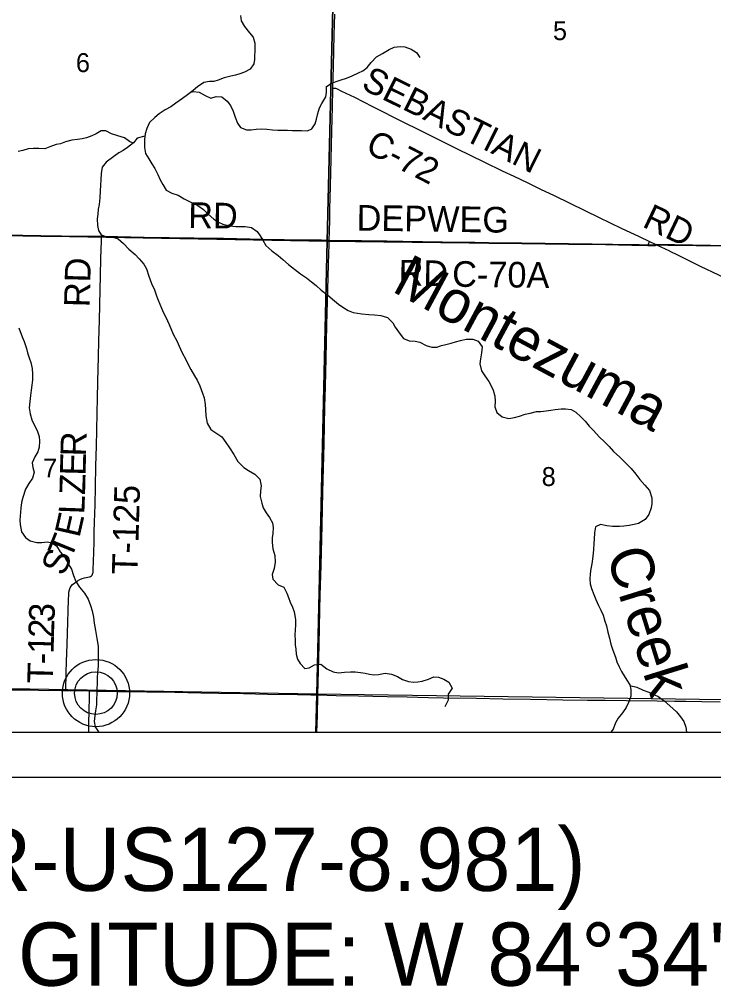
# Model space of a CAD drawing. Extents: x -38.1 to 35.9, y -2.7 to 28.5.
# Drawn here: x 22.334 to 23.873, y 12.367 to 14.509 of the extents above; entities that cross this region are included whole.
import ezdxf

# ---------------------------------------------------------------- set-up
doc = ezdxf.new("R2010")
doc.units = 0
for name, color, linetype in [('GM_X_City_Street_Text', 7, 'Continuous'), ('GM_X_County_ROW', 7, 'Continuous'), ('GM_X_Interchange_Ramps', 7, 'Continuous'), ('GM_X_Major_River_Text', 7, 'Continuous'), ('GM_X_Minor_Lake', 7, 'Continuous'), ('GM_X_Minor_River', 7, 'Continuous'), ('GM_X_Section', 7, 'Continuous'), ('GM_X_State_Location', 7, 'Continuous'), ('GM_X_Township', 7, 'Continuous'), ('GM_X_US_Location', 7, 'Continuous'), ('GM_X_US_Route', 7, 'Continuous'), ('SH_Border', 7, 'Continuous'), ('SH_Data', 7, 'Continuous')]:
    doc.layers.add(name, color=color, linetype=linetype)

msp = doc.modelspace()

# ---------------------------------------------------------------- linework, layer by layer
at = {"layer": 'GM_X_City_Street_Text'}
for points in [[(23.0287, 14.3566), (23.03, 14.4044), (23.0321, 14.4746), (23.0332, 14.5205)], [(23.0207, 14.0188), (23.022, 14.0627), (23.0222, 14.0788), (23.0224, 14.0906), (23.023, 14.1122), (23.0242, 14.1689), (23.0264, 14.2615), (23.0279, 14.3149), (23.0286, 14.3534), (23.0287, 14.3566)], [(23.0287, 14.3566), (23.0304, 14.3567), (23.0319, 14.3567), (23.0328, 14.3567), (23.0338, 14.3565), (23.0348, 14.3563), (23.0368, 14.3554), (23.0481, 14.3501), (23.0765, 14.3361), (23.1165, 14.316), (23.1376, 14.3054), (23.1648, 14.2918), (23.188, 14.2798), (23.217, 14.2656), (23.2714, 14.2382), (23.3025, 14.2226), (23.3651, 14.1922), (23.4037, 14.1737), (23.4295, 14.1613), (23.4592, 14.1472), (23.4889, 14.133), (23.5192, 14.1185), (23.5869, 14.0857), (23.6188, 14.0703), (23.6674, 14.0467), (23.7073, 14.0278), (23.7303, 14.0169)], [(21.9177, 14.0374), (21.9429, 14.0367), (21.9873, 14.0362), (22.0447, 14.0351), (22.0942, 14.0343), (22.1484, 14.0334), (22.1956, 14.0323), (22.2832, 14.031), (22.3422, 14.0297), (22.3821, 14.029), (22.4276, 14.0284), (22.5162, 14.0274)], [(22.5162, 14.0274), (22.5224, 14.0273), (22.6112, 14.0255), (22.7218, 14.0237), (22.7522, 14.0232), (22.787, 14.0228), (22.8454, 14.0218), (22.8745, 14.021), (22.9684, 14.0196), (23.0035, 14.0189), (23.0162, 14.0188), (23.0207, 14.0188), (23.0927, 14.0177), (23.1488, 14.0168), (23.184, 14.0165), (23.2716, 14.0153), (23.2727, 14.0153)], [(22.9956, 13.013), (22.9968, 13.0663), (22.9975, 13.093), (22.9991, 13.1601), (22.9999, 13.2029), (23.0009, 13.2334), (23.0027, 13.3005), (23.0051, 13.3881), (23.0065, 13.462), (23.0089, 13.5421), (23.0094, 13.5688), (23.0112, 13.6509), (23.0124, 13.6962), (23.0138, 13.7577), (23.0157, 13.8323), (23.0179, 13.9099), (23.0193, 13.9664), (23.0204, 14.0111), (23.0207, 14.0188)], [(23.2727, 14.0153), (23.3437, 14.014), (23.3741, 14.0135), (23.4474, 14.0125), (23.551, 14.0113), (23.6034, 14.0107), (23.6914, 14.009)], [(23.6914, 14.009), (23.6935, 14.009), (23.7264, 14.0084), (23.7326, 14.0083), (23.7379, 14.0082), (23.7407, 14.0081), (23.7425, 14.0082), (23.7439, 14.0083), (23.7451, 14.0088), (23.746, 14.0095)], [(23.7264, 14.0084), (23.7275, 14.0097), (23.7284, 14.0112), (23.7291, 14.0129), (23.7297, 14.0147), (23.7303, 14.0169)], [(23.7303, 14.0169), (23.7418, 14.0115), (23.746, 14.0095)], [(23.746, 14.0095), (23.7556, 14.005), (23.7744, 13.9959), (23.7752, 13.9955)], [(23.7752, 13.9955), (23.7925, 13.9872), (23.8427, 13.9625), (23.8836, 13.9429), (23.9373, 13.9169), (24.0117, 13.8809), (24.0233, 13.8753)], [(22.9935, 12.9308), (22.9945, 12.9673), (22.9956, 13.013)]]:
    msp.add_lwpolyline(points, dxfattribs=at)
at = {"layer": 'GM_X_County_ROW'}
msp.add_line((22.5039, 13.0171), (22.5039, 13.0171), dxfattribs=at)
at = {"layer": 'GM_X_Interchange_Ramps'}
for p, q in [((22.437, 13.0226), (22.4897, 13.0219)), ((22.4897, 13.0219), (22.4979, 13.0218))]:
    msp.add_line(p, q, dxfattribs=at)
for points in [[(21.893, 13.0338), (21.8997, 13.0337), (21.9581, 13.0327), (21.9941, 13.0317), (22.0314, 13.0308), (22.0637, 13.0299), (22.1177, 13.0288), (22.1917, 13.0273), (22.2252, 13.0264), (22.2867, 13.0251), (22.3091, 13.0247), (22.3122, 13.0246), (22.3352, 13.0244), (22.3581, 13.024), (22.3768, 13.0237), (22.4268, 13.0227), (22.437, 13.0226)], [(22.4979, 13.0218), (22.5072, 13.0216), (22.5287, 13.0213), (22.554, 13.0209), (22.578, 13.0205), (22.6168, 13.0201), (22.6498, 13.0196), (22.7361, 13.0178), (22.7752, 13.0171), (22.8311, 13.0159), (22.8839, 13.0148), (22.9503, 13.0139), (22.9801, 13.0133), (22.9956, 13.013), (23.0365, 13.0121), (23.0858, 13.0111), (23.1488, 13.0096), (23.1935, 13.0087), (23.2407, 13.0077), (23.2743, 13.0068), (23.3469, 13.0056), (23.4058, 13.0048), (23.4667, 13.0036), (23.5385, 13.0024), (23.593, 13.0018), (23.6321, 13.0014), (23.6793, 13.0008), (23.7477, 12.9997), (23.7855, 12.9992), (23.811, 12.9989), (23.8464, 12.9983), (23.8868, 12.998)]]:
    msp.add_lwpolyline(points, dxfattribs=at)
at = {"layer": 'GM_X_Major_River_Text'}
msp.add_line((22.4897, 13.0219), (22.437, 13.0226), dxfattribs=at)
for points in [[(22.437, 13.0226), (22.4379, 13.0626), (22.4387, 13.0865), (22.4402, 13.1255), (22.4411, 13.1498), (22.4431, 13.2235), (22.4435, 13.2353), (22.444, 13.2409), (22.4452, 13.2459), (22.447, 13.25), (22.4493, 13.2538), (22.4523, 13.2572), (22.457, 13.2614), (22.4627, 13.2654), (22.4682, 13.2685), (22.4734, 13.2708), (22.4783, 13.2722), (22.4863, 13.2736), (22.4898, 13.2745), (22.492, 13.2752), (22.4939, 13.2765), (22.4953, 13.2782), (22.4966, 13.2807), (22.4971, 13.2824), (22.4974, 13.2842), (22.498, 13.2903), (22.4988, 13.3091), (22.4993, 13.3287), (22.4998, 13.352), (22.5002, 13.3743), (22.5008, 13.3956), (22.5019, 13.4338), (22.5028, 13.4741), (22.5038, 13.5195), (22.505, 13.5642), (22.5056, 13.5984), (22.5066, 13.6381), (22.507, 13.6692), (22.5082, 13.7071), (22.5097, 13.7617), (22.5105, 13.7972), (22.5116, 13.8425), (22.5131, 13.9102), (22.5138, 13.9419), (22.5148, 13.9792), (22.5159, 14.0183), (22.516, 14.0214), (22.5162, 14.0274)], [(22.4879, 12.9308), (22.4883, 12.9566), (22.4886, 12.9721), (22.4895, 13.0151), (22.4897, 13.0219)]]:
    msp.add_lwpolyline(points, dxfattribs=at)
at = {"layer": 'GM_X_Section'}
for points in [[(22.8245, 14.5174), (22.8258, 14.5056), (22.8331, 14.4929), (22.8442, 14.4786), (22.8519, 14.469), (22.8558, 14.4563), (22.856, 14.4465), (22.8554, 14.4199), (22.8537, 14.41), (22.8458, 14.3984), (22.8327, 14.3915), (22.8228, 14.3883), (22.8132, 14.3855), (22.8029, 14.3827), (22.788, 14.3796), (22.775, 14.3742), (22.7651, 14.3714), (22.7552, 14.3708), (22.7433, 14.3688), (22.7287, 14.3593), (22.719, 14.3511), (22.7067, 14.3419), (22.6954, 14.3334), (22.6812, 14.3235), (22.6696, 14.315), (22.6573, 14.3081), (22.6442, 14.2992), (22.6345, 14.2915), (22.6225, 14.2803), (22.6165, 14.2672), (22.6128, 14.2551), (22.6114, 14.243), (22.6114, 14.2247), (22.6137, 14.2118), (22.6211, 14.1998), (22.6277, 14.1886), (22.6343, 14.1782), (22.6408, 14.1652), (22.6459, 14.1533), (22.6521, 14.1433), (22.6594, 14.1302), (22.6722, 14.1238), (22.6858, 14.1193), (22.6997, 14.1114), (22.7098, 14.1059), (22.72, 14.1011), (22.7297, 14.0967), (22.7421, 14.088), (22.7525, 14.0775), (22.7652, 14.0666), (22.7753, 14.0595), (22.7851, 14.0555), (22.8006, 14.0518), (22.8142, 14.0503), (22.8347, 14.0498), (22.8483, 14.0476), (22.8614, 14.0394), (22.8681, 14.0297), (22.8736, 14.0197), (22.8801, 14.0078)], [(22.7145, 14.3477), (22.7201, 14.3488), (22.7326, 14.3474), (22.7457, 14.3403), (22.7582, 14.3343), (22.77, 14.3382), (22.7829, 14.3375), (22.7949, 14.3278), (22.8019, 14.3177), (22.808, 14.3054), (22.8123, 14.2924), (22.8177, 14.279), (22.824, 14.2694), (22.8375, 14.2641), (22.8478, 14.2643), (22.8588, 14.2655), (22.8714, 14.266), (22.8824, 14.2654), (22.8949, 14.2643), (22.907, 14.2637), (22.9169, 14.2635), (22.9283, 14.2636), (22.9393, 14.263), (22.9591, 14.2625), (22.9727, 14.2618), (22.9823, 14.2666), (22.9898, 14.2774), (22.9927, 14.288), (22.9956, 14.3005), (22.9993, 14.3125), (23.0041, 14.3227), (23.0135, 14.3373), (23.0149, 14.3475), (23.0151, 14.3597), (23.0252, 14.3667), (23.0359, 14.3714), (23.047, 14.3749), (23.0592, 14.3784), (23.0715, 14.3839), (23.0853, 14.39), (23.0953, 14.3944), (23.105, 14.4021), (23.114, 14.4133), (23.1256, 14.426), (23.1387, 14.4329), (23.1533, 14.4421), (23.1649, 14.4475), (23.1782, 14.4483), (23.1884, 14.4481), (23.2027, 14.4425), (23.2143, 14.435), (23.2217, 14.4242)], [(22.5863, 14.2344), (22.5786, 14.238), (22.567, 14.2462), (22.5523, 14.2511), (22.5387, 14.2556), (22.5256, 14.2616), (22.5157, 14.2622), (22.5045, 14.2556), (22.4949, 14.2505), (22.4831, 14.2462), (22.4731, 14.2442), (22.4628, 14.2425), (22.4503, 14.2409), (22.4365, 14.2378), (22.4254, 14.2335), (22.4155, 14.2314), (22.4021, 14.2268), (22.391, 14.2221), (22.3777, 14.2228), (22.3659, 14.223), (22.3534, 14.2218), (22.3419, 14.2186), (22.3316, 14.2158)], [(22.6122, 14.2502), (22.5955, 14.246), (22.5873, 14.2352), (22.5741, 14.2248), (22.5641, 14.2186), (22.5545, 14.2131), (22.5433, 14.205), (22.5267, 14.1924), (22.5177, 14.1816), (22.5155, 14.1672), (22.5145, 14.1536), (22.5138, 14.1418), (22.5132, 14.1293), (22.5128, 14.1133), (22.511, 14.0985), (22.5092, 14.0883), (22.5082, 14.0773), (22.5069, 14.0671), (22.5073, 14.0523), (22.5093, 14.0416), (22.5156, 14.0319), (22.5261, 14.0279), (22.539, 14.0272), (22.553, 14.0231), (22.5653, 14.0126), (22.5768, 13.9998), (22.591, 13.988), (22.5999, 13.9783), (22.6099, 13.9667), (22.6161, 13.9563), (22.6211, 13.9402), (22.6272, 13.9241), (22.6333, 13.9099), (22.638, 13.8969), (22.6419, 13.8869), (22.6495, 13.8693), (22.6539, 13.8589), (22.6586, 13.8493), (22.6662, 13.8328), (22.6753, 13.8117), (22.6829, 13.7967), (22.6909, 13.7786), (22.6956, 13.769), (22.7022, 13.7575), (22.7065, 13.7479), (22.7142, 13.7336), (22.7226, 13.7194), (22.7281, 13.7098), (22.7343, 13.6971), (22.74, 13.681), (22.7436, 13.671), (22.7456, 13.6561), (22.7464, 13.6447), (22.7473, 13.6306), (22.7507, 13.6146), (22.7588, 13.6007), (22.7696, 13.5932), (22.7827, 13.5842), (22.7916, 13.5718), (22.8001, 13.5602), (22.8096, 13.5452), (22.818, 13.5302), (22.8318, 13.5166), (22.8419, 13.5102), (22.8562, 13.5019), (22.8673, 13.4907), (22.8697, 13.4758), (22.8687, 13.4651), (22.868, 13.4522), (22.8711, 13.4373), (22.8747, 13.4274), (22.8809, 13.4162), (22.8887, 13.4061), (22.8952, 13.3938), (22.8969, 13.3839), (22.8959, 13.3706), (22.8945, 13.3608), (22.8943, 13.3509), (22.8955, 13.3368), (22.9001, 13.3218), (22.9013, 13.307), (22.8991, 13.293), (22.8943, 13.2798), (22.8959, 13.2694), (22.9075, 13.257), (22.9202, 13.2514), (22.9272, 13.2383), (22.9304, 13.2287), (22.9343, 13.2184), (22.9394, 13.2072), (22.9434, 13.1969), (22.9464, 13.1797), (22.9462, 13.1675), (22.9456, 13.1569), (22.9449, 13.1455), (22.9451, 13.1349), (22.9456, 13.1242), (22.9469, 13.1143), (22.9474, 13.1036), (22.9506, 13.0925), (22.9561, 13.0825)], [(22.8801, 14.0078), (22.8935, 13.9961), (22.9078, 13.9862), (22.9182, 13.9769), (22.9305, 13.966), (22.944, 13.9558), (22.957, 13.9456), (22.9705, 13.9362), (22.9813, 13.9276), (22.9918, 13.9197), (23.0029, 13.9089), (23.0168, 13.8987), (23.028, 13.8889), (23.041, 13.8783), (23.053, 13.8697), (23.0628, 13.8645), (23.0737, 13.8597), (23.0835, 13.858), (23.0934, 13.8566), (23.1085, 13.8555), (23.1214, 13.8549), (23.1354, 13.8534), (23.1498, 13.8485), (23.1617, 13.8365), (23.1668, 13.8269), (23.1782, 13.8118), (23.1856, 13.8021), (23.198, 13.7973), (23.2113, 13.7962), (23.2215, 13.7937), (23.2358, 13.7869), (23.2479, 13.7832), (23.2589, 13.7833), (23.2696, 13.7865), (23.2792, 13.789), (23.291, 13.7921), (23.3009, 13.7946), (23.3116, 13.7974), (23.3242, 13.8005), (23.3387, 13.8006), (23.3511, 13.7961), (23.3596, 13.7834), (23.3585, 13.7701), (23.3556, 13.7572), (23.3546, 13.7462), (23.3584, 13.7309), (23.3658, 13.7193), (23.3742, 13.707), (23.3797, 13.6974), (23.3841, 13.6878), (23.3876, 13.6747), (23.3881, 13.6637), (23.3878, 13.6512), (23.3925, 13.6385), (23.404, 13.6284), (23.4184, 13.6254), (23.4314, 13.6274), (23.4425, 13.6302), (23.4551, 13.6344), (23.4662, 13.6372), (23.4799, 13.6403), (23.4898, 13.6409), (23.5012, 13.6418), (23.5115, 13.6434), (23.5214, 13.6451), (23.5347, 13.6463), (23.5446, 13.6465), (23.5571, 13.6447), (23.5672, 13.6391), (23.5784, 13.629), (23.5881, 13.6189), (23.597, 13.6084), (23.6062, 13.5983), (23.6192, 13.5847), (23.6304, 13.5734), (23.6412, 13.5629), (23.6508, 13.5521), (23.665, 13.5396), (23.6795, 13.5244), (23.6895, 13.5143), (23.6999, 13.5015), (23.7087, 13.4899), (23.7199, 13.4771), (23.7302, 13.4655), (23.7356, 13.4494), (23.7357, 13.4372), (23.734, 13.427), (23.7287, 13.4126), (23.7205, 13.4018), (23.7062, 13.3926), (23.6963, 13.3905), (23.6856, 13.3885), (23.6735, 13.3869), (23.6639, 13.3856), (23.6487, 13.3859), (23.6355, 13.3877), (23.6219, 13.3903), (23.6111, 13.3849), (23.6082, 13.372), (23.6075, 13.3579), (23.6073, 13.3481)], [(22.3329, 13.8255), (22.3404, 13.8059), (22.3448, 13.7952), (22.3497, 13.7802), (22.3526, 13.7703), (22.3561, 13.7596), (22.3597, 13.7492), (22.3628, 13.7355), (22.3637, 13.7229), (22.3634, 13.7104), (22.362, 13.699), (22.3603, 13.688), (22.3592, 13.6759), (22.3571, 13.6626), (22.356, 13.6489), (22.358, 13.6352), (22.3622, 13.6218), (22.3746, 13.5964), (22.3778, 13.5853), (22.3791, 13.575), (22.3784, 13.5614), (22.3755, 13.5512), (22.3688, 13.5399), (22.3628, 13.5267), (22.3641, 13.5165), (22.3673, 13.5065), (22.3632, 13.4929), (22.3554, 13.4813), (22.3479, 13.4685), (22.3418, 13.4504), (22.3393, 13.4391), (22.3375, 13.4269), (22.3365, 13.4175), (22.3354, 13.4), (22.3359, 13.3905), (22.339, 13.3744), (22.3475, 13.3617), (22.3579, 13.3542), (22.3731, 13.3505), (22.3841, 13.3502), (22.3959, 13.3519), (22.4065, 13.3501)], [(22.4065, 13.3501), (22.4162, 13.343), (22.4247, 13.3299), (22.4339, 13.3187), (22.4438, 13.3013), (22.45, 13.2913), (22.4543, 13.2775), (22.4593, 13.2641), (22.4678, 13.2514), (22.4789, 13.2382), (22.487, 13.2251), (22.4916, 13.2113), (22.4952, 13.1994), (22.4983, 13.1853), (22.5003, 13.1723), (22.5029, 13.1559), (22.506, 13.1379), (22.5087, 13.1211), (22.5091, 13.1063), (22.5092, 13.0922), (22.5085, 13.0778), (22.5074, 13.0618), (22.5068, 13.052), (22.5065, 13.0379), (22.5059, 13.0276), (22.5056, 13.0155), (22.505, 13.0037), (22.5051, 12.9915), (22.5033, 12.9775), (22.5015, 12.9677), (22.5001, 12.954), (22.5021, 12.9422), (22.5099, 12.9313), (22.5103, 12.9308)], [(23.6073, 13.3481), (23.6062, 13.3348), (23.6048, 13.3192), (23.6029, 13.3033), (23.6007, 13.2919), (23.5986, 13.2813), (23.598, 13.2692), (23.5989, 13.2589), (23.6021, 13.2489), (23.6067, 13.2355), (23.6118, 13.2247), (23.6172, 13.2109), (23.6223, 13.2009), (23.6274, 13.1894), (23.6317, 13.1767), (23.6353, 13.1664), (23.6384, 13.1522), (23.6419, 13.1384), (23.645, 13.1251), (23.6493, 13.112), (23.6554, 13.0967), (23.6582, 13.0863), (23.6629, 13.0756), (23.6684, 13.0652), (23.6739, 13.0555), (23.6805, 13.0455), (23.6868, 13.0351), (23.6892, 13.0252), (23.6893, 13.0103), (23.6836, 12.9964), (23.6788, 12.9854), (23.6706, 12.9738), (23.6612, 12.9619), (23.6549, 12.951), (23.6501, 12.9374), (23.6449, 12.9308)], [(22.9561, 13.0825), (22.9665, 13.0716), (22.976, 13.0729), (22.9883, 13.0795), (23.002, 13.0811), (23.0155, 13.0709), (23.0294, 13.0641), (23.0415, 13.0623), (23.0545, 13.0632), (23.0678, 13.064), (23.0784, 13.0641), (23.0902, 13.0631), (23.1004, 13.0614), (23.1102, 13.0589), (23.1197, 13.0579), (23.1299, 13.0584), (23.1444, 13.0615), (23.1588, 13.0589), (23.172, 13.0536), (23.1833, 13.0469), (23.1961, 13.0425), (23.2075, 13.0414), (23.217, 13.042), (23.2265, 13.0433), (23.2407, 13.0483), (23.2529, 13.053), (23.2628, 13.0523), (23.2745, 13.0483), (23.2857, 13.0412), (23.293, 13.0277), (23.2844, 13.0146), (23.2841, 13.0013), (23.2766, 12.9866)], [(23.687, 13.0341), (23.7022, 13.0306), (23.7165, 13.0234), (23.729, 13.0189), (23.7387, 13.0141), (23.7489, 13.0101), (23.7631, 13.0003), (23.7754, 12.9893), (23.7903, 12.9753), (23.7988, 12.9648), (23.8062, 12.954), (23.8109, 12.9417), (23.8121, 12.9308)]]:
    msp.add_lwpolyline(points, dxfattribs=at)
at = {"layer": 'GM_X_State_Location'}
for radius in [0.0744, 0.0472]:
    msp.add_circle((22.5039, 13.0171), radius, dxfattribs=at)
at = {"layer": 'GM_X_US_Route'}
for points in [[(21.9409, 15.0133), (23.0396, 14.9923), (23.0161, 14.0176), (21.9144, 14.0375)], [(23.0396, 14.9923), (24.0515, 14.9714), (24.0218, 14.0056), (23.0161, 14.0176)], [(21.9144, 14.0375), (23.0161, 14.0176), (22.9932, 13.0145), (21.8896, 13.0337), (21.9134, 14.0076)], [(23.0161, 14.0176), (24.0218, 14.0056), (23.9996, 13.0005), (22.9932, 13.0145)], [(21.8874, 12.9308), (22.991, 12.9308), (22.9932, 13.0145), (21.8896, 13.0337), (21.8889, 13.0056)], [(22.991, 12.9308), (23.9977, 12.9308), (23.9996, 13.0005), (22.9932, 13.0145)]]:
    msp.add_lwpolyline(points, close=True, dxfattribs=at)
for points in [[(22.283, 14.0315), (22.3419, 14.0302), (22.3819, 14.0296), (22.4274, 14.0289), (22.516, 14.0279), (22.5221, 14.0279), (22.6109, 14.026), (22.7215, 14.0242), (22.752, 14.0237), (22.7867, 14.0233), (22.8451, 14.0223), (22.8743, 14.0216), (22.9681, 14.0201), (23.0033, 14.0195), (23.0159, 14.0194), (23.0204, 14.0194), (23.0925, 14.0182), (23.1486, 14.0174), (23.1838, 14.017), (23.2714, 14.0158), (23.3435, 14.0145), (23.3739, 14.0141), (23.4472, 14.0131), (23.5508, 14.0118), (23.6032, 14.0112), (23.6932, 14.0096), (23.7262, 14.009), (23.7323, 14.0089), (23.7377, 14.0087), (23.7405, 14.0086), (23.7423, 14.0087), (23.7437, 14.0089), (23.7448, 14.0094), (23.7458, 14.01), (24.0256, 14.0048)], [(24.0256, 14.0048), (23.7458, 14.01), (23.7448, 14.0094), (23.7437, 14.0089), (23.7423, 14.0087), (23.7405, 14.0086), (23.7377, 14.0087), (23.7323, 14.0089), (23.7262, 14.009), (23.6932, 14.0096), (23.6032, 14.0112), (23.5508, 14.0118), (23.4472, 14.0131), (23.3739, 14.0141), (23.3435, 14.0145), (23.2714, 14.0158), (23.1838, 14.017), (23.1486, 14.0174), (23.0925, 14.0182), (23.0204, 14.0194), (23.0159, 14.0194), (23.0033, 14.0195), (22.9681, 14.0201), (22.8743, 14.0216), (22.8451, 14.0223), (22.7867, 14.0233), (22.752, 14.0237), (22.7215, 14.0242), (22.6109, 14.026), (22.5221, 14.0279), (22.516, 14.0279), (22.4274, 14.0289), (22.3819, 14.0296), (22.3419, 14.0302), (22.283, 14.0315)], [(21.8901, 12.9308), (25.4101, 12.9308)]]:
    msp.add_lwpolyline(points, dxfattribs=at)
at = {"layer": 'SH_Border'}
msp.add_line((18.6101, 12.9308), (25.4101, 12.9308), dxfattribs=at)
at = {"layer": 'SH_Data'}
msp.add_line((18.5101, 12.8308), (25.5101, 12.8308), dxfattribs=at)

# ---------------------------------------------------------------- texts
at = {"layer": 'GM_X_Minor_Lake'}
for s, height, rotation, p in [('RD', 0.05682, 359.0171, (22.7079, 14.0471)), ('RD', 0.05682, 88.5315, (22.49, 13.871)), ('R', 0.0568, 88.4816, (22.4819, 13.5406)), ('E', 0.0568, 88.4806, (22.4808, 13.4981)), ('Z', 0.0568, 88.4837, (22.4797, 13.4556)), ('T-125', 0.05682, 88.3143, (22.5959, 13.2788)), ('L', 0.0568, 87.9333, (22.4781, 13.4125)), ('E', 0.0568, 77.2349, (22.4672, 13.3596)), ('T', 0.0568, 67.8237, (22.4481, 13.3106)), ('S', 0.0568, 66.8538, (22.4327, 13.2743)), ('3', 0.0568, 87.5638, (22.4117, 13.1733)), ('2', 0.0568, 88.436, (22.4108, 13.1386)), ('1', 0.0568, 88.6312, (22.41, 13.1036)), ('-', 0.0568, 88.6846, (22.4094, 13.0803)), ('T', 0.0568, 88.6949, (22.4085, 13.0378))]:
    msp.add_text(s, height=height, rotation=rotation, dxfattribs=at).set_placement(p)
at = {"layer": 'GM_X_Minor_River'}
for s, p in [('5', (23.5165, 14.4628)), ('6', (22.4595, 14.3919)), ('7', (22.387, 13.4945)), ('8', (23.4915, 13.4756))]:
    msp.add_text(s, height=0.0419, rotation=0, dxfattribs=at).set_placement(p)
at = {"layer": 'GM_X_Township'}
for s, rotation, p in [('SEBASTIAN', 333.5433, (23.0894, 14.3562)), ('C-72', 333.1316, (23.098, 14.2161)), ('DEPWEG', 359.1746, (23.0811, 14.0412)), ('RD', 334.5155, (23.7122, 14.0506)), ('RD', 359.0362, (23.174, 13.9196)), ('C-70A', 359.242, (23.2929, 13.9169))]:
    msp.add_text(s, height=0.05682, rotation=rotation, dxfattribs=at).set_placement(p)
at = {"layer": 'GM_X_US_Location'}
for s, height, rotation, p in [('Montezuma', 0.09472, 331.711, (23.1568, 13.908)), ('Creek', 0.09484, 287.2379, (23.634, 13.3256))]:
    msp.add_text(s, height=height, rotation=rotation, dxfattribs=at).set_placement(p)
at = {"layer": 'SH_Data'}
for s, p in [('LOCATION MAP (MER-US127-8.981)', (20.4156, 12.5792)), ('LATITUDE: N 40°29\'01"    LONGITUDE: W 84°34\'17" ', (19.7401, 12.3692))]:
    msp.add_text(s, height=0.14, dxfattribs=at).set_placement(p)

doc.saveas('drawing.dxf')
